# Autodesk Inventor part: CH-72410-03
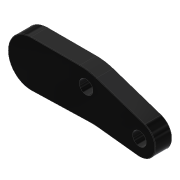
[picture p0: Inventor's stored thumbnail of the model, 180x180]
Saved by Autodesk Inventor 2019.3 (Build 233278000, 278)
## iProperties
Created: 2012-10
Part Number: CH-72410-03
Material: Ogólny
Document SubType Name: Modeling
Designer: CADENGINEERING4
Density: 1 g/cm^3
Appearance: Gładki — czarny
Author: CADENGINEERING4
Revision Number: ÈÎºÎ
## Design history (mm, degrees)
feature "Ô²½Ç1"
node "Bryła1"
